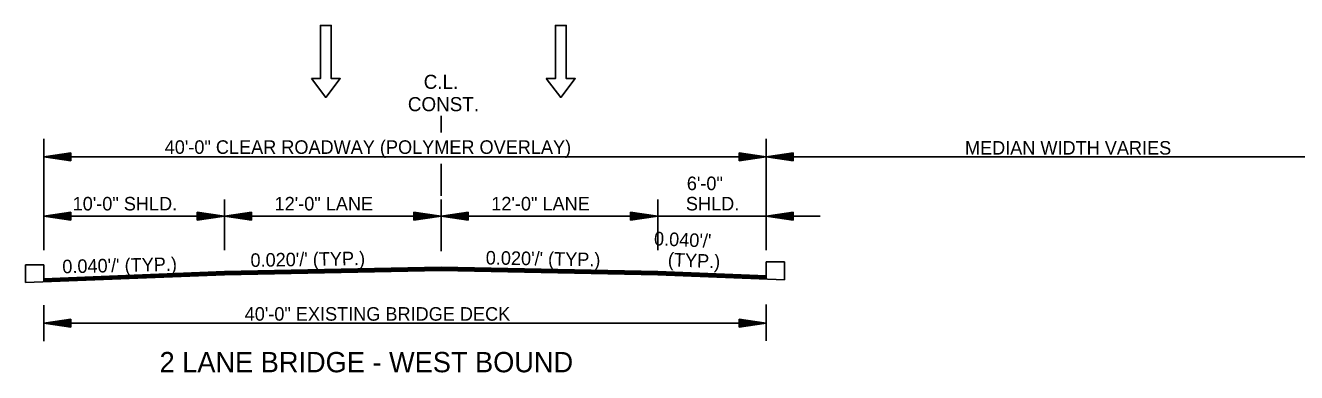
# Model space of a CAD drawing. Extents: x 550980 to 1930787, y -1972975 to 596640.
# Drawn here: x 551138 to 551842, y -1962177 to -1961985 of the extents above; entities that cross this region are included whole.
import ezdxf

# ---------------------------------------------------------------- set-up
doc = ezdxf.new("R2010")
doc.units = 0
doc.layers.add('R_Border', color=7, linetype='Continuous')
doc.layers.add('R_Draft', color=7, linetype='Continuous')

msp = doc.modelspace()

# ---------------------------------------------------------------- linework, layer by layer
at = {"layer": 'R_Border'}
for p, q in [((551148.24, -1962117.68), (551138.08, -1962117.68)), ((551138.08, -1962117.68), (551138.08, -1962127.5)), ((551148.24, -1962127.09), (551148.24, -1962117.68)), ((551548.24, -1962125.32), (551548.24, -1962115.91)), ((551548.24, -1962115.91), (551558.41, -1962115.91)), ((551558.41, -1962115.91), (551558.41, -1962125.9))]:
    msp.add_line(p, q, dxfattribs=at)
for points in [[(551296.41, -1962014.54), (551304.41, -1962024.93), (551312.41, -1962014.54), (551307.41, -1962014.54), (551307.41, -1961985.12), (551301.41, -1961985.12), (551301.41, -1962014.54)], [(551426.53, -1962014.54), (551434.53, -1962024.93), (551442.53, -1962014.54), (551437.53, -1962014.54), (551437.53, -1961985.12), (551431.53, -1961985.12), (551431.53, -1962014.54)]]:
    msp.add_lwpolyline(points, close=True, dxfattribs=at)
at = {"layer": 'R_Draft'}
for p, q in [((551368.24, -1962044.46), (551368.24, -1962035.16)), ((551148.24, -1962109.47), (551148.24, -1962047.98)), ((551548.24, -1962109.47), (551548.24, -1962047.98)), ((551163.24, -1962055.63), (551148.24, -1962057.88)), ((551163.24, -1962055.63), (551163.24, -1962060.13)), ((551533.24, -1962055.63), (551548.24, -1962057.88)), ((551533.24, -1962060.13), (551533.24, -1962055.63)), ((551563.24, -1962055.63), (551548.24, -1962057.88)), ((551563.24, -1962055.63), (551563.24, -1962060.13)), ((551548.24, -1962057.88), (551148.24, -1962057.88)), ((551163.24, -1962060.13), (551148.24, -1962057.88)), ((551163.24, -1962056), (551150.75, -1962057.88)), ((551163.24, -1962059.75), (551150.75, -1962057.88)), ((551163.24, -1962056.38), (551153.33, -1962057.88)), ((551163.24, -1962059.37), (551153.33, -1962057.88)), ((551163.24, -1962056.76), (551155.83, -1962057.88)), ((551163.24, -1962058.99), (551155.83, -1962057.88)), ((551163.24, -1962057.15), (551158.37, -1962057.88)), ((551163.24, -1962058.61), (551158.37, -1962057.88)), ((551163.24, -1962057.52), (551160.87, -1962057.88)), ((551163.24, -1962058.23), (551160.87, -1962057.88)), ((551508.24, -1962057.88), (551228.24, -1962057.88)), ((551368.24, -1962079.4), (551368.24, -1962061.64)), ((551533.24, -1962056), (551545.74, -1962057.88)), ((551533.24, -1962056.38), (551543.16, -1962057.88)), ((551533.24, -1962056.76), (551540.66, -1962057.88)), ((551533.24, -1962057.14), (551538.12, -1962057.88)), ((551533.24, -1962057.52), (551535.61, -1962057.88)), ((551533.24, -1962060.13), (551548.24, -1962057.88)), ((551533.24, -1962058.6), (551538.12, -1962057.88)), ((551533.24, -1962059.37), (551543.16, -1962057.88)), ((551533.24, -1962059.75), (551545.74, -1962057.88)), ((551533.24, -1962058.99), (551540.66, -1962057.88)), ((551533.24, -1962058.23), (551535.61, -1962057.88)), ((551563.24, -1962060.13), (551548.24, -1962057.88)), ((551888.24, -1962057.88), (551548.24, -1962057.88)), ((551563.24, -1962056), (551550.75, -1962057.88)), ((551563.24, -1962059.75), (551550.75, -1962057.88)), ((551563.24, -1962056.38), (551553.33, -1962057.88)), ((551563.24, -1962059.37), (551553.33, -1962057.88)), ((551563.24, -1962056.76), (551555.83, -1962057.88)), ((551563.24, -1962058.99), (551555.83, -1962057.88)), ((551563.24, -1962057.15), (551558.37, -1962057.88)), ((551563.24, -1962058.61), (551558.37, -1962057.88)), ((551563.24, -1962057.52), (551560.87, -1962057.88)), ((551563.24, -1962058.23), (551560.87, -1962057.88)), ((551248.24, -1962109.47), (551248.24, -1962081.52)), ((551368.24, -1962109.47), (551368.24, -1962081.52)), ((551368.24, -1962110.07), (551368.24, -1962081.52)), ((551488.24, -1962109.47), (551488.24, -1962081.52)), ((551163.24, -1962088.46), (551148.24, -1962090.71)), ((551248.24, -1962090.71), (551148.24, -1962090.71)), ((551163.24, -1962092.96), (551148.24, -1962090.71)), ((551163.24, -1962088.84), (551150.75, -1962090.71)), ((551163.24, -1962092.59), (551150.75, -1962090.71)), ((551163.24, -1962089.22), (551153.33, -1962090.71)), ((551163.24, -1962092.2), (551153.33, -1962090.71)), ((551163.24, -1962089.59), (551155.83, -1962090.71)), ((551163.24, -1962091.83), (551155.83, -1962090.71)), ((551163.24, -1962089.98), (551158.37, -1962090.71)), ((551163.24, -1962091.45), (551158.37, -1962090.71)), ((551163.24, -1962090.36), (551160.87, -1962090.71)), ((551163.24, -1962091.06), (551160.87, -1962090.71)), ((551163.24, -1962088.46), (551163.24, -1962092.96)), ((551233.24, -1962088.46), (551248.24, -1962090.71)), ((551233.24, -1962088.46), (551233.24, -1962092.96)), ((551233.24, -1962088.84), (551245.74, -1962090.71)), ((551233.24, -1962089.22), (551243.16, -1962090.71)), ((551233.24, -1962089.59), (551240.66, -1962090.71)), ((551233.24, -1962089.98), (551238.12, -1962090.71)), ((551233.24, -1962090.36), (551235.61, -1962090.71)), ((551233.24, -1962092.96), (551248.24, -1962090.71)), ((551233.24, -1962091.45), (551238.12, -1962090.71)), ((551233.24, -1962092.2), (551243.16, -1962090.71)), ((551233.24, -1962092.59), (551245.74, -1962090.71)), ((551233.24, -1962091.83), (551240.66, -1962090.71)), ((551233.24, -1962091.06), (551235.61, -1962090.71)), ((551263.24, -1962088.46), (551248.24, -1962090.71)), ((551368.24, -1962090.71), (551248.24, -1962090.71)), ((551263.24, -1962092.96), (551248.24, -1962090.71)), ((551263.24, -1962088.84), (551250.75, -1962090.71)), ((551263.24, -1962092.59), (551250.75, -1962090.71)), ((551263.24, -1962089.22), (551253.33, -1962090.71)), ((551263.24, -1962092.2), (551253.33, -1962090.71)), ((551263.24, -1962089.59), (551255.83, -1962090.71)), ((551263.24, -1962091.83), (551255.83, -1962090.71)), ((551263.24, -1962089.98), (551258.37, -1962090.71)), ((551263.24, -1962091.45), (551258.37, -1962090.71)), ((551263.24, -1962090.36), (551260.87, -1962090.71)), ((551263.24, -1962091.06), (551260.87, -1962090.71)), ((551263.24, -1962088.46), (551263.24, -1962092.96)), ((551353.24, -1962088.46), (551368.24, -1962090.71)), ((551353.24, -1962088.46), (551353.24, -1962092.96)), ((551353.24, -1962088.84), (551365.74, -1962090.71)), ((551353.24, -1962089.22), (551363.16, -1962090.71)), ((551353.24, -1962089.59), (551360.66, -1962090.71)), ((551353.24, -1962089.98), (551358.12, -1962090.71)), ((551353.24, -1962090.36), (551355.61, -1962090.71)), ((551353.24, -1962092.96), (551368.24, -1962090.71)), ((551353.24, -1962091.45), (551358.12, -1962090.71)), ((551353.24, -1962092.2), (551363.16, -1962090.71)), ((551353.24, -1962092.59), (551365.74, -1962090.71)), ((551353.24, -1962091.83), (551360.66, -1962090.71)), ((551353.24, -1962091.06), (551355.61, -1962090.71)), ((551383.24, -1962088.46), (551368.24, -1962090.71)), ((551488.24, -1962090.71), (551368.24, -1962090.71)), ((551383.24, -1962092.96), (551368.24, -1962090.71)), ((551383.24, -1962088.84), (551370.75, -1962090.71)), ((551383.24, -1962092.59), (551370.75, -1962090.71)), ((551383.24, -1962089.22), (551373.33, -1962090.71)), ((551383.24, -1962092.2), (551373.33, -1962090.71)), ((551383.24, -1962089.59), (551375.83, -1962090.71)), ((551383.24, -1962091.83), (551375.83, -1962090.71)), ((551383.24, -1962089.98), (551378.37, -1962090.71)), ((551383.24, -1962091.45), (551378.37, -1962090.71)), ((551383.24, -1962090.36), (551380.87, -1962090.71)), ((551383.24, -1962091.06), (551380.87, -1962090.71)), ((551383.24, -1962088.46), (551383.24, -1962092.96)), ((551473.24, -1962088.46), (551488.24, -1962090.71)), ((551473.24, -1962088.46), (551473.24, -1962092.96)), ((551473.24, -1962088.84), (551485.74, -1962090.71)), ((551473.24, -1962089.22), (551483.16, -1962090.71)), ((551473.24, -1962089.59), (551480.66, -1962090.71)), ((551473.24, -1962089.98), (551478.12, -1962090.71)), ((551473.24, -1962090.36), (551475.61, -1962090.71)), ((551473.24, -1962092.96), (551488.24, -1962090.71)), ((551473.24, -1962091.45), (551478.12, -1962090.71)), ((551473.24, -1962092.2), (551483.16, -1962090.71)), ((551473.24, -1962092.59), (551485.74, -1962090.71)), ((551473.24, -1962091.83), (551480.66, -1962090.71)), ((551473.24, -1962091.06), (551475.61, -1962090.71)), ((551548.24, -1962090.71), (551488.24, -1962090.71)), ((551563.24, -1962088.46), (551548.24, -1962090.71)), ((551563.24, -1962092.96), (551548.24, -1962090.71)), ((551548.24, -1962090.71), (551578.24, -1962090.71)), ((551563.24, -1962088.84), (551550.75, -1962090.71)), ((551563.24, -1962092.59), (551550.75, -1962090.71)), ((551563.24, -1962089.22), (551553.33, -1962090.71)), ((551563.24, -1962092.2), (551553.33, -1962090.71)), ((551563.24, -1962089.59), (551555.83, -1962090.71)), ((551563.24, -1962091.83), (551555.83, -1962090.71)), ((551563.24, -1962089.98), (551558.37, -1962090.71)), ((551563.24, -1962091.45), (551558.37, -1962090.71)), ((551563.24, -1962090.36), (551560.87, -1962090.71)), ((551563.24, -1962091.06), (551560.87, -1962090.71)), ((551563.24, -1962088.46), (551563.24, -1962092.96)), ((551368.24, -1962119.02), (551248.24, -1962121.42)), ((551368.24, -1962119.02), (551488.24, -1962121.42)), ((551248.24, -1962123.09), (551138.08, -1962127.5)), ((551248.24, -1962121.42), (551148.24, -1962125.42)), ((551248.24, -1962121.72), (551148.24, -1962125.72)), ((551248.24, -1962122.02), (551148.24, -1962126.02)), ((551248.24, -1962122.32), (551148.24, -1962126.32)), ((551248.24, -1962122.62), (551148.24, -1962126.62)), ((551248.24, -1962122.92), (551148.24, -1962126.92)), ((551368.24, -1962119.32), (551248.24, -1962121.72)), ((551368.24, -1962119.62), (551248.24, -1962122.02)), ((551368.24, -1962119.92), (551248.24, -1962122.32)), ((551368.24, -1962120.22), (551248.24, -1962122.62)), ((551368.24, -1962120.52), (551248.24, -1962122.92)), ((551368.24, -1962120.69), (551248.24, -1962123.09)), ((551368.24, -1962119.32), (551488.24, -1962121.72)), ((551368.24, -1962119.62), (551488.24, -1962122.02)), ((551368.24, -1962119.92), (551488.24, -1962122.32)), ((551368.24, -1962120.22), (551488.24, -1962122.62)), ((551368.24, -1962120.52), (551488.24, -1962122.92)), ((551368.24, -1962120.69), (551488.24, -1962123.09)), ((551488.24, -1962121.42), (551548.24, -1962123.82)), ((551488.24, -1962121.72), (551548.24, -1962124.12)), ((551488.24, -1962122.02), (551548.24, -1962124.42)), ((551488.24, -1962122.32), (551548.24, -1962124.72)), ((551488.24, -1962122.62), (551548.24, -1962125.02)), ((551488.24, -1962122.92), (551548.24, -1962125.32)), ((551488.24, -1962123.09), (551558.41, -1962125.9)), ((551148.24, -1962139.88), (551148.24, -1962159.88)), ((551548.24, -1962139.63), (551548.24, -1962159.63)), ((551163.24, -1962147.63), (551148.24, -1962149.88)), ((551163.24, -1962152.13), (551148.24, -1962149.88)), ((551538.24, -1962149.88), (551148.24, -1962149.88)), ((551163.24, -1962148), (551150.75, -1962149.88)), ((551163.24, -1962151.75), (551150.75, -1962149.88)), ((551163.24, -1962148.39), (551153.33, -1962149.88)), ((551163.24, -1962151.37), (551153.33, -1962149.88)), ((551163.24, -1962148.76), (551155.83, -1962149.88)), ((551163.24, -1962151), (551155.83, -1962149.88)), ((551163.24, -1962149.15), (551158.37, -1962149.88)), ((551163.24, -1962150.61), (551158.37, -1962149.88)), ((551163.24, -1962149.53), (551160.87, -1962149.88)), ((551163.24, -1962150.23), (551160.87, -1962149.88)), ((551163.24, -1962147.63), (551163.24, -1962152.13)), ((551533.24, -1962147.63), (551548.24, -1962149.88)), ((551533.24, -1962152.13), (551533.24, -1962147.63)), ((551533.24, -1962148), (551545.74, -1962149.88)), ((551533.24, -1962148.39), (551543.16, -1962149.88)), ((551533.24, -1962148.76), (551540.66, -1962149.88)), ((551533.24, -1962149.14), (551538.12, -1962149.88)), ((551533.24, -1962149.53), (551535.61, -1962149.88)), ((551533.24, -1962152.13), (551548.24, -1962149.88)), ((551533.24, -1962150.61), (551538.12, -1962149.88)), ((551533.24, -1962151.37), (551543.16, -1962149.88)), ((551533.24, -1962151.75), (551545.74, -1962149.88)), ((551533.24, -1962151), (551540.66, -1962149.88)), ((551533.24, -1962150.23), (551535.61, -1962149.88))]:
    msp.add_line(p, q, dxfattribs=at)

# ---------------------------------------------------------------- texts
for s, height, p in [('C.L.', 7.8, (551358.64, -1962020.22)), ('CONST.', 7.8, (551349.86, -1962032.59)), ('40\'-0" CLEAR ROADWAY (POLYMER OVERLAY)', 7.5, (551215.21, -1962056.21)), ('MEDIAN WIDTH VARIES', 7.5, (551658.36, -1962056.61)), ('6\'-0"', 7.5, (551504.34, -1962076.29)), ('10\'-0" SHLD.', 7.5, (551164.23, -1962087.54)), ('12\'-0" LANE', 7.5, (551276.06, -1962087.54)), ('12\'-0" LANE', 7.5, (551396.06, -1962087.54)), ('SHLD.', 7.5, (551503.83, -1962087.54)), ('40\'-0" EXISTING BRIDGE DECK', 7.5, (551259.5, -1962148.56)), ('2 LANE BRIDGE - WEST BOUND', 11.25, (551212.36, -1962177.12))]:
    msp.add_text(s, height=height, dxfattribs=at).set_placement(p)
for s, rotation, p in [("  0.040'/'", 357.55203, (551480.48, -1962106.56)), ("0.020'/' (TYP.)", 0.97192, (551262.77, -1962118.82)), ("0.020'/' (TYP.)", 359.02808, (551392.95, -1962117.44)), (' (TYP.)', 357.55203, (551490.94, -1962118.26)), ("0.040'/' (TYP.)", 1.31838, (551158.59, -1962122.36))]:
    msp.add_text(s, height=7.5, rotation=rotation, dxfattribs=at).set_placement(p)

doc.saveas('drawing.dxf')
